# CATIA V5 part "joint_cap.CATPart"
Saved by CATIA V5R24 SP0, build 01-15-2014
Part number: Part1
Bounding box of the stored display mesh (mm): x -30 to 30, y -30 to 30, z 0 to 69.58
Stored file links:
  D:\OneDrive\01_COURSE WORK\2019-1\CAD\models\joint_cap.CATPart
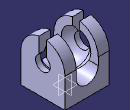
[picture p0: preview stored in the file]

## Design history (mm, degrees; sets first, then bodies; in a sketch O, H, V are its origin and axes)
Body1 (main body)
  Sketch1 on xy-plane, origin (0, 0, 0), H (1, 0, 0), V (0, 1, 0)
    line L1 (30, 30) -> (30, -30)
    line L2 (30, -30) -> (-30, -30)
    line L3 (-30, -30) -> (-30, 30)
    line L4 (-30, 30) -> (30, 30)
    distance L2 L4 = 60
    distance L1 L3 = 60
    vertical: L1 V, L3 V
    horizontal: L2 H, L4 H
    equidistance: L1 L3 O, L2 L4 O
  Pad1: profile Sketch1, direction (0, 0, 1), length 70
  Sketch2 on yz-plane, origin (0, 0, 0), H (0, 1, 0), V (0, 0, 1)
    arc A1 centre (0, 40) radius 30 from (30, 39.9999) to (-30, 39.9999) ccw
    point P1 (0, 40)
    point P2 (30, 39.9999)
    point P3 (-30, 39.9999)
    reference projected line E1 (30, 0) -> (30, 70) from edge [face of Pad1 from Sketch1.L4 | face of Pad1 from Sketch1.L1]
    reference projected line E2 (-30, 0) -> (-30, 70) from edge [face of Pad1 from Sketch1.L1 | face of Pad1 from Sketch1.L2]
    distance P1 H = 40
    radius A1 = 30
    coincidence: P1 V, P2 E1, P3 E2
  Pocket1: profile Sketch2, direction (-1, 0, 0), through (limit type 3), opposite side through (limit type 3)
  Sketch3 on zx-plane, origin (0, 0, 0), H (-1, 0, 0), V (0, 0, 1)
    line L1 (-15, 71.1403) -> (-15, 30)
    arc A1 centre (0, 30) radius 15 from (-15, 30) to (15, 30) ccw
    point P3 (0, 30)
    line L2 (15, 30) -> (15, 71.1403)
    distance L1 V = 15
    distance P3 H = 30
    vertical: L1 V
    tangency: A1 L1, L2 A1
    symmetry: L1 L2 V
  Pocket2: profile Sketch3, direction (0, -1, 0), through (limit type 3), opposite side through (limit type 3)
  Sketch4 on zx-plane, origin (0, 0, 0), H (-1, 0, 0), V (0, 0, 1)
    arc A1 centre (0, 40) radius 25 from (0, 15) to (15, 60) ccw
    point P1 (0, 40)
    point P2 (15, 60)
    axis line L1 (0, 74.455) -> (0, -11.8853)
    point P3 (0, 74.455)
    point P5 (0, 15)
    reference projected line E1 (15, 39.9999) -> (15, 70) from edge [face of Pocket1 | face of Pocket2 from Sketch3.L2]
    radius A1 = 25
    distance P1 H = 40
    coincidence: P1 V, P3 V, L1 P5, P2 E1
    vertical: L1 V
  Groove1: profile Sketch4, axis Sketch4.L1, angle 360
  Sketch5 on yz-plane, origin (0, 0, 0), H (0, 1, 0), V (0, 0, 1)
    construction line L1 (0, 40) -> (0, 75)
    point P1 (0, 40)
    point P2 (0, 75)
    line L2 (5, 75) -> (5, 48.6603)
    line L3 (-5, 48.6603) -> (-5, 75)
    arc A1 centre (0, 40) radius 10 from (5, 48.6603) to (-5, 48.6603) cw
    arc A2 centre (0, 75) radius 5 from (-5, 75) to (5, 75) cw
    reference projected arc E1 centre (0, 40) radius 30 from (30, 39.9999) to (-30, 39.9999) ccw from edge [face of Pad1 from Sketch1.L1 | face of Pocket1]
    radius A1 = 10
    radius A2 = 5
    distance P1 H = 40
    distance P2 E1 = 5
    coincidence: P1 V
    vertical: L1 V
    tangency: A2 L2, A2 L3
    parallelism: L2 L3, L2 L1
  Pocket3: profile Sketch5, direction (-1, 0, 0), through (limit type 3), opposite side through (limit type 3)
